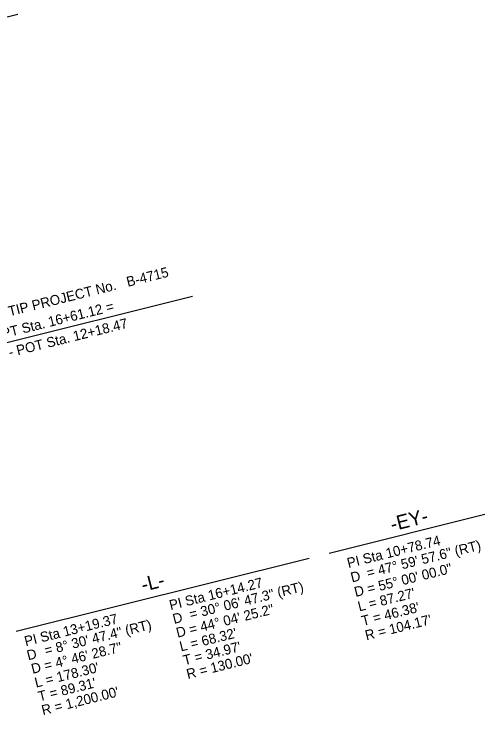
# Model space of a CAD drawing. Extents: x 1030774 to 1032138, y 656382 to 657027.
# Drawn here: x 1031805.9 to 1032137.6, y 656527.8 to 657021.2 of the extents above; entities that cross this region are included whole.
import ezdxf

# ---------------------------------------------------------------- set-up
doc = ezdxf.new("R2010")
doc.units = 0
for name, color, linetype in [('Exist Horizontal Alignment Curve and Spiral Data', 7, 'Continuous'), ('Exist Horizontal Alignment Station Label', 7, 'Continuous'), ('Prop Horizontal Alignment Curve and Spiral Data', 7, 'Continuous'), ('Prop Horizontal Alignment Station Label', 7, 'Continuous')]:
    doc.layers.add(name, color=color, linetype=linetype)

msp = doc.modelspace()

# ---------------------------------------------------------------- linework, layer by layer
at = {"layer": 'Exist Horizontal Alignment Station Label'}
for p, q in [((1031706.16, 656995.66), (1031808.52, 657021.19)), ((1032027.82, 656641.75), (1032137.55, 656669.11))]:
    msp.add_line(p, q, dxfattribs=at)
at = {"layer": 'Prop Horizontal Alignment Curve and Spiral Data'}
msp.add_line((1031807.38, 656586.79), (1032013.82, 656638.26), dxfattribs=at)
at = {"layer": 'Prop Horizontal Alignment Station Label'}
msp.add_line((1031556, 656728.88), (1031931.5, 656822.46), dxfattribs=at)

# ---------------------------------------------------------------- texts
at = {"layer": 'Exist Horizontal Alignment Curve and Spiral Data'}
for s, p in [('PI Sta 10+78.74', (1032041.38, 656631.2)), ('= 47%%d 59\' 57.6" (RT)', (1032055.24, 656624.24)), ('D = 55%%d 00\' 00.0"', (1032046.46, 656610.82)), ('D', (1032043.92, 656621.01)), ("L = 87.27'", (1032049, 656600.63)), ("T = 46.38'", (1032051.54, 656590.45)), ("R = 104.17'", (1032054.08, 656580.26))]:
    msp.add_text(s, height=7, rotation=14, dxfattribs=at).set_placement(p)
at = {"layer": 'Exist Horizontal Alignment Station Label'}
msp.add_text('-EY-', height=10, rotation=14, dxfattribs=at).set_placement((1032072.29, 656656.98))
at = {"layer": 'Prop Horizontal Alignment Curve and Spiral Data'}
for s, height, p in [('-L-', 10, (1031896.85, 656614.44)), ('PI Sta 16+14.27', 7, (1031916.19, 656601.53)), ('= 30%%d 06\' 47.3" (RT)', 7, (1031930.36, 656595.06)), ('D = 44%%d 04\' 25.2"', 7, (1031921.03, 656582.13)), ('PI Sta 13+19.37', 7, (1031814.14, 656576.09)), ('D', 7, (1031918.61, 656591.83)), ('= 8%%d 30\' 47.4" (RT)', 7, (1031828.3, 656569.62)), ("L = 68.32'", 7, (1031923.45, 656572.42)), ('D = 4%%d 46\' 28.7"', 7, (1031818.98, 656556.68)), ("T = 34.97'", 7, (1031925.87, 656562.72)), ('D', 7, (1031815.9, 656566.22)), ("R = 130.00'", 7, (1031928.29, 656553.02)), ("L = 178.30'", 7, (1031821.4, 656546.98)), ("T = 89.31'", 7, (1031823.82, 656537.28)), ("R = 1,200.00'", 7, (1031826.24, 656527.57))]:
    msp.add_text(s, height=height, rotation=14, dxfattribs=at).set_placement(p)
at = {"layer": 'Prop Horizontal Alignment Station Label'}
for s, p in [('END TIP PROJECT No.   B-4715', (1031781.05, 656802.93)), ('-L- PT Sta. 16+61.12 =', (1031784.44, 656789.35)), ('-EY- POT Sta. 12+18.47', (1031787.82, 656775.76))]:
    msp.add_text(s, height=7, rotation=14, dxfattribs=at).set_placement(p)

doc.saveas('drawing.dxf')
